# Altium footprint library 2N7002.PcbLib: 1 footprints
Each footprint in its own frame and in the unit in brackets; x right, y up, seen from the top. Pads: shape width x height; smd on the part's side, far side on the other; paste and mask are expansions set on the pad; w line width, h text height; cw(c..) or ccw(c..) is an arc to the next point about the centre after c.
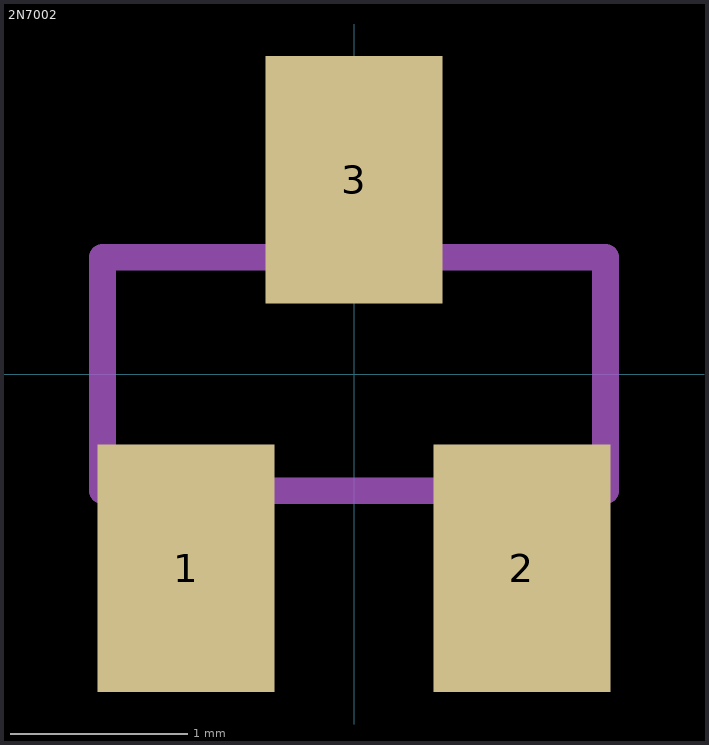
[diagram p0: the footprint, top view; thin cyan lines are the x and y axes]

## 2N7002 [mm]
pads (3):
  rect 1x1.4 smd: 1(-0.95,-1.1) 2(0.95,-1.1) 3(0,1.1)
Mechanical 13:
  region: 0.229,0.711 -0.229,0.711 -0.229,1.295 0.229,1.295
  region: 1.168,-1.297 0.712,-1.297 0.712,-0.711 1.168,-0.711
  region: -0.711,-1.297 -1.17,-1.297 -1.17,-0.711 -0.711,-0.711
  lines w0.152: -1.422,-0.66 1.422,-0.66 1.422,0.66 -1.422,0.66 -1.422,-0.66
3D body "2N7002.STEP": height 1.24, standoff -0.01, extent -1.46,-1.374 1.466,1.426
